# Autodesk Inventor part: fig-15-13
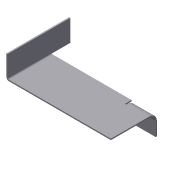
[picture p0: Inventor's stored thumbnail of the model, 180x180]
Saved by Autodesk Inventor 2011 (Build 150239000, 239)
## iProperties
Shininess: 77.0
Angle Display Precision: 2
Document Length Units: 11269
Document Angle Units: 11279
Document Time Units: 11290
Document Mass Units: 11283
Document Length Units Precision: 3
Document Angle Units Precision: 2
Created: 2002-04
Part Number: fig-15-13
Material: Aluminum-6061
Document SubType Name: Sheet Metal
Density: 1 g/cm^3
Sheet Metal Rule: Default
Density: 0.0
Volumn: 0.0
Area: 0.0
PropertySet Name: Model Information
Control State: 0
Master: False
Checked Out: False
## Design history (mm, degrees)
node "Face1"
  sketch "Sketch1"
    geometry: L1 (-49.559, 19.574)-(-49.559, -30.426); L2 (-49.559, -30.426)-(50.441, -30.426); L3 (50.441, -30.426)-(50.441, 19.574); L4 (50.441, 19.574)-(32.941, 19.574); L5 (32.941, 19.574)-(32.941, 4.574); L6 (32.941, 4.574)-(-32.059, 4.574); L7 (-32.059, 4.574)-(-32.059, 19.574); L8 (-32.059, 19.574)-(-49.559, 19.574)
    constraints: 16 end point, 6 parallel, 2 equal length, 1 perpendicular, 1 vertical
    dimensions: "d0" = 100 distance of L1.end L2.end; "d1" = 65 distance of L5.end L6.end; "d2" = 15 distance of L6.end L7.end; "d3" = 50 distance of L1.start L1.end
sketch "Sketch2"
  geometry: L1 (100, 0)-(0, 0) reference; L2 (17.5, 50)-(17.5, 35) reference; L3 (82.5, 50)-(82.5, 0)
  constraints: 2 end point, 1 parallel, 1 point on line
sketch "Sketch3"
  geometry: L1 (81.369, -50)-(0, -50) reference; L2 (17.5, 0)-(17.5, -50)
  constraints: 2 end point, 1 perpendicular, 1 point on line
feature "Fold2" sketch "Sketch3" dims "d8" = 1 (= BendRadius), "d9" = 90 deg, "d10" = 1 (= BendRadius), "d14" = 1 (= BendReliefWidth), "d15" = 0.5 (= BendReliefDepth), "d16" = 2 (= MinimumRemnant), "SeamGap" = 0.01, "Thickness" = 1
sketch "Sketch4"
  geometry: L1 (17.5, 0)-(17.5, -50) reference; L2 (-63.869, -15)-(0, -15) reference; L3 (0, -15)-(17.5, -15)
  constraints: 2 end point, 1 collinear, 1 point on line
feature "Fold3" sketch "Sketch4" dims "d11" = 1 (= BendRadius), "d12" = 90 deg, "d13" = 5, "d17" = 1 (= BendReliefWidth), "d18" = 1, "d19" = 2 (= MinimumRemnant), "SeamGap" = 0.01, "Thickness" = 1
body "Solid1"
face "Plate1" dims "Thickness" = 1
other parameters: "BendRadius" = 1 (= Thickness), "BendReliefWidth" = 1 (= Thickness), "BendReliefDepth" = 0.5 (= 0.5 x Thickness), "CornerReliefSize" = 4 (= 4 x Thickness), "MinimumRemnant" = 2 (= 2 x Thickness), "TransitionRadius" = 1 (= BendRadius), "d4" = 1 (= BendRadius), "JacobiRadiusSize" = 1 (= Thickness), "GapSize" = 1 (= Thickness)
